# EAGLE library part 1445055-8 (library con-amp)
Micro MATE-N-LOK Connectors grid 1.5 mm Source: ENG_CD_1445055_A.pdf
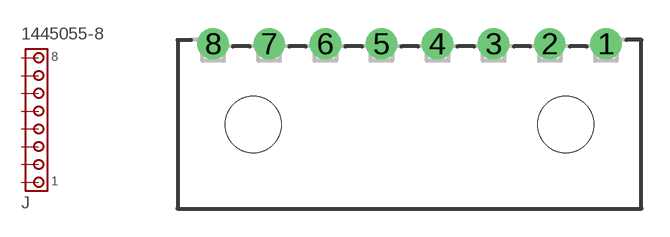
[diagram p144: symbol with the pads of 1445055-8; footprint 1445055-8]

Designator prefix J

## 1445055-8 (MPN: 2-1445055-8; OC_FARNELL: unknown; OC_NEWARK: 17R5937)  [1445055-8]
1  1  pas
2  2  pas
3  3  pas
4  4  pas
5  5  pas
6  6  pas
7  7  pas
8  8  pas

## Footprint 1445055-8 (pad centres in mm)
Micro MATE-N-LOK Connectors grid 3.0 mm Source: ENG_CD_1445055_A.pdf
drill 1 pad 1.676 round: 1 10.5,4.32; 2 7.5,4.32; 3 4.5,4.32; 4 1.5,4.32; 5 -1.5,4.32; 6 -4.5,4.32; 7 -7.5,4.32; 8 -10.5,4.32
hole 3 at -8.35,0
hole 3 at 8.35,0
